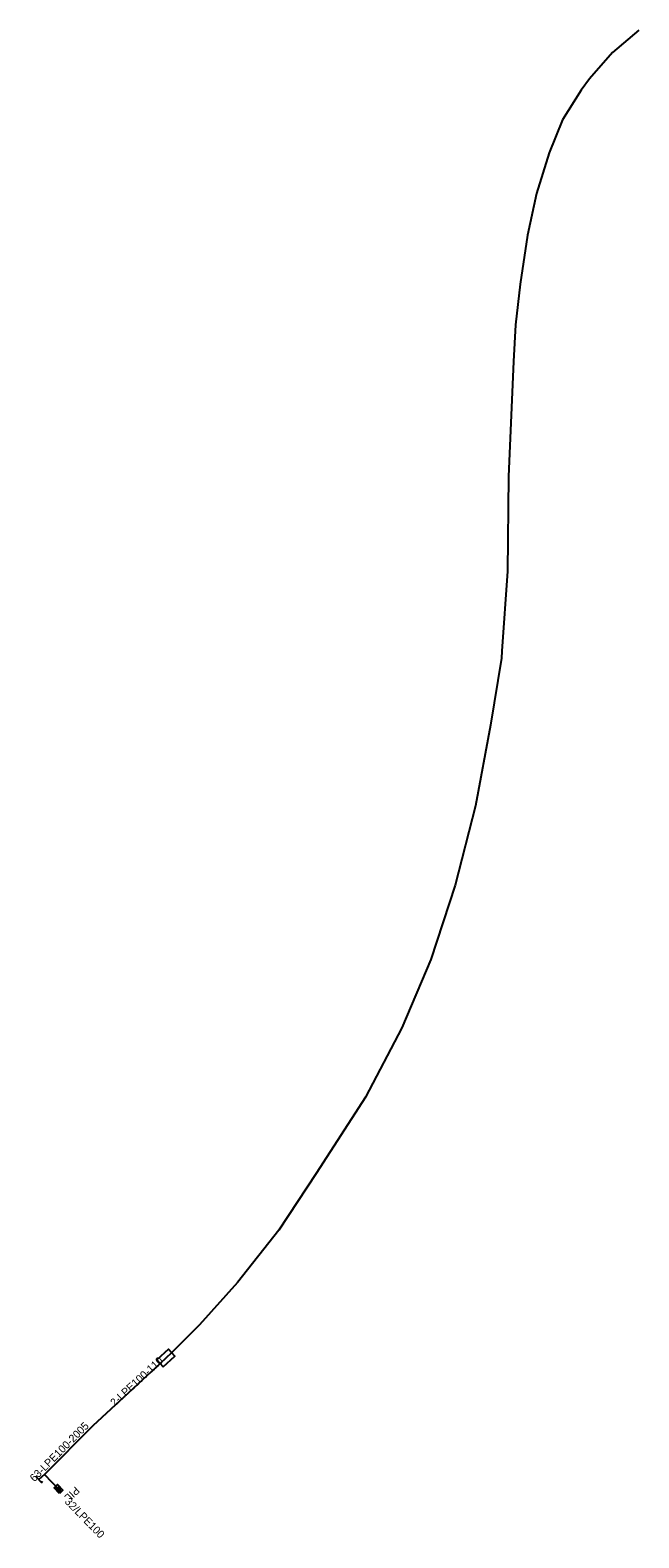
# Model space of a CAD drawing. Extents: x -762921 to -762499, y -1152946 to -1152170.
# Drawn here: x -762920.6 to -762842, y -1152364.9 to -1152170.3 of the extents above; entities that cross this region are included whole.
import ezdxf

# ---------------------------------------------------------------- set-up
doc = ezdxf.new("R2010")
doc.units = 0
for name, color, linetype in [('Vrstva 21', 7, 'Continuous'), ('Vrstva 23', 7, 'Continuous'), ('Vrstva 29', 7, 'Continuous'), ('Vrstva 31', 7, 'Continuous'), ('Vrstva 32', 7, 'Continuous')]:
    doc.layers.add(name, color=color, linetype=linetype)

msp = doc.modelspace()

# ---------------------------------------------------------------- linework, layer by layer
at = {"layer": 'Vrstva 21'}
msp.add_lwpolyline([(-762842.01, -1152170.27), (-762845.39, -1152173.17), (-762848.38, -1152176.56), (-762849.47, -1152178.02), (-762851.88, -1152181.86), (-762853.59, -1152186.09), (-762855.24, -1152191.35), (-762856.39, -1152196.74), (-762857.35, -1152203.08), (-762857.94, -1152208.32), (-762858.21, -1152213.06), (-762858.83, -1152227.92), (-762858.97, -1152240.14), (-762859.69, -1152250.45), (-762859.75, -1152251.35), (-762861.18, -1152260), (-762863.08, -1152270.42), (-762865.71, -1152280.65), (-762868.86, -1152290.25), (-762872.62, -1152299.08), (-762877.3, -1152308.04), (-762883.66, -1152317.9), (-762888.49, -1152325.21), (-762893.81, -1152331.98), (-762898.71, -1152337.44), (-762902.33, -1152341.03), (-762903.83, -1152342.41), (-762912.52, -1152350.46), (-762918.76, -1152356.77), (-762919.49, -1152357.41)], dxfattribs=at)
at = {"layer": 'Vrstva 23'}
msp.add_lwpolyline([(-762919.693, -1152356.911), (-762919.837, -1152357.05), (-762919.144, -1152357.771), (-762919, -1152357.632)], dxfattribs=at)
at = {"layer": 'Vrstva 29'}
msp.add_lwpolyline([(-762903.42, -1152342.85), (-762901.92, -1152341.47), (-762902.74, -1152340.59), (-762904.24, -1152341.97)], close=True, dxfattribs=at)
at = {"layer": 'Vrstva 31'}
msp.add_lwpolyline([(-762918.76, -1152356.77), (-762916.94, -1152358.64)], dxfattribs=at)
at = {"layer": 'Vrstva 32'}
for p, q in [((-762916.952, -1152358.375), (-762917.205, -1152358.616)), ((-762916.676, -1152358.663), (-762916.929, -1152358.905)), ((-762916.671, -1152358.936), (-762916.81, -1152358.791)), ((-762916.79, -1152359.05), (-762916.537, -1152358.809))]:
    msp.add_line(p, q, dxfattribs=at)
for points in [[(-762916.812, -1152359.209), (-762917.502, -1152358.486), (-762917.068, -1152358.071), (-762916.378, -1152358.795), (-762916.812, -1152359.209)], [(-762917.205, -1152358.616), (-762917.294, -1152358.522), (-762917.311, -1152358.48), (-762917.31, -1152358.458), (-762917.296, -1152358.425), (-762917.26, -1152358.391), (-762917.226, -1152358.378), (-762917.204, -1152358.378), (-762917.163, -1152358.397), (-762917.073, -1152358.491)], [(-762916.998, -1152358.833), (-762916.816, -1152358.66), (-762916.79, -1152358.616), (-762916.788, -1152358.571), (-762916.804, -1152358.529), (-762916.824, -1152358.508), (-762916.866, -1152358.489), (-762916.91, -1152358.491), (-762916.955, -1152358.515), (-762917.136, -1152358.688)]]:
    msp.add_lwpolyline(points, dxfattribs=at)

# ---------------------------------------------------------------- texts
at = {"layer": 'Vrstva 21'}
msp.add_text('63-LPE100-2005', height=1, rotation=45.31958, dxfattribs=at).set_placement((-762920.04, -1152357.77))
at = {"layer": 'Vrstva 29'}
msp.add_text('2-LPE100-110', height=1, rotation=42.61406, dxfattribs=at).set_placement((-762909.69, -1152348.03))
at = {"layer": 'Vrstva 31'}
msp.add_text('32/LPE100', height=1, rotation=314.22368, dxfattribs=at).set_placement((-762916.21, -1152360.34))
msp.add_text('32/LPE100', height=1, rotation=314.22368, dxfattribs=at).set_placement((-762916.21, -1152360.34))
at = {"layer": 'Vrstva 32'}
msp.add_text('PIL', height=1, rotation=223.67568, dxfattribs=at).set_placement((-762914.78, -1152358.23))
msp.add_text('PIL', height=1, rotation=223.67568, dxfattribs=at).set_placement((-762914.78, -1152358.23))

doc.saveas('drawing.dxf')
